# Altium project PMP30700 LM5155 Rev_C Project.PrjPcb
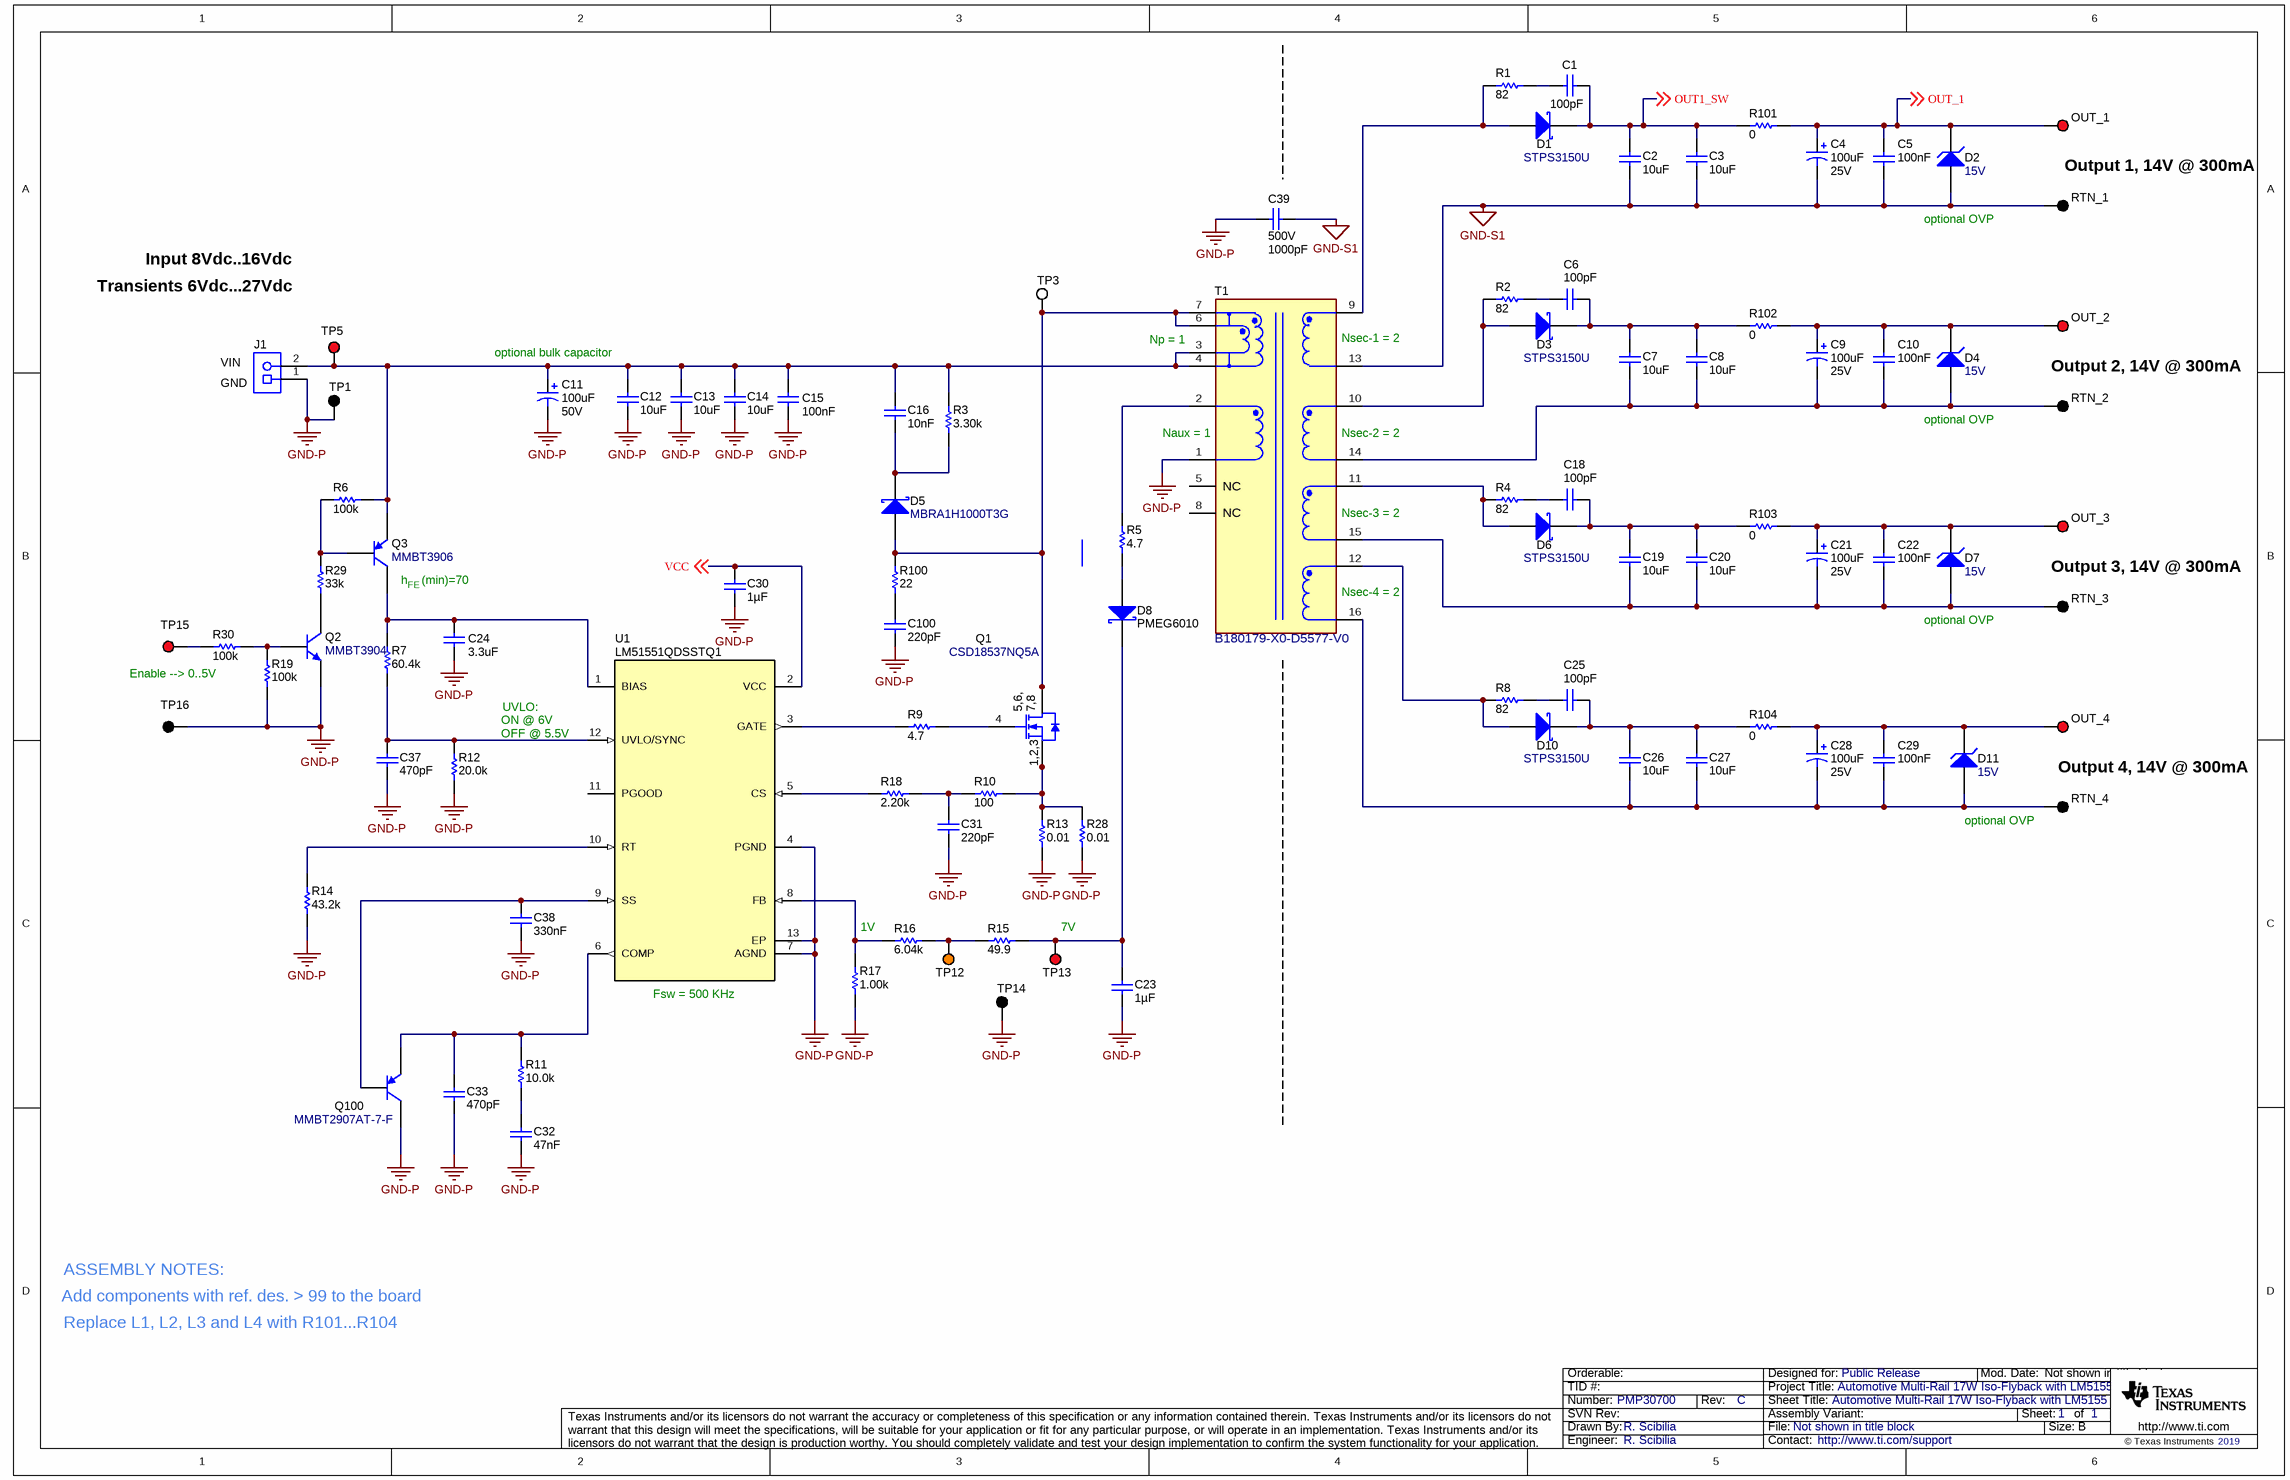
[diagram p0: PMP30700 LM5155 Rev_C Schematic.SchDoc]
CopyrightYear: 2019; PCB_Layout: PMP30700 LM5155; PCB_Rev: A; PRJ_Customer: Public Release; PRJ_Engineer: R. Scibilia; PRJ_Number: PMP30700; PRJ_Title: Automotive Multi-Rail 17W Iso-Flyback with LM5155; SCH_Rev: C; TechSupport: http://www.ti.com/support
1 sheet, 96 parts. Net scope: global (net labels, ports and power ports of the same name join across sheets).
Board file: PMP30700 Rev_A PCB.PcbDoc

## Sheet PMP30700 LM5155 Rev_C Schematic.SchDoc: Automotive Multi-Rail 17W Iso-Flyback with LM5155
size 431 x 279 mm; Date: Not shown in title block; ApprovedBy: Not shown in title block; CheckedBy: Not shown in title block; Author: Not shown in title block; CompanyName: Not shown in title block; DrawnBy: R. Scibilia; Engineer: Not shown in title block; Organization: Not shown in title block; Address1: Not shown in title block; Address2: Not shown in title block; Address3: Not shown in title block; Address4: Not shown in title block; DocumentNumber: 1; Revision: Use project parameter SCH_Rev; SheetNumber: 1; SheetTotal: 1; PageSetup: Record=PageOptions¦CenterHorizontal=True¦CenterVertical=True¦PrintScale=1.00¦XCorrection=1.00¦YCorrection=1.00¦PrintKind=0¦BorderSize=5000000¦LeftOffset=0¦BottomOffset=0¦Orientation=2¦PaperLength=1000¦PaperWidth=1000¦Scale=100¦PaperSource=15¦PrintQuality=600¦MediaType=1¦DitherType=10¦PaperKind=Letter¦PrintScaleMode=1

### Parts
C1  ValueDisplayed: 100pF  [0805_HV]  (hidden comment: GRM21A5C2E101JW01D)
C2  ValueDisplayed: 10uF  [1210_270]  (hidden comment: GRM32ER71H106KA12L)
C3  ValueDisplayed: 10uF  [1210_270]  (hidden comment: GRM32ER71H106KA12L)
C4  VDC_V: 25V  ValueDisplayed: 100uF  [SVPF_E7]  (hidden comment: 25SVPF100M)
C5  Cap_F: 100nF  [0603]  (hidden comment: GCM188R71H104KA57D)
C6  ValueDisplayed: 100pF  [0805_HV]  (hidden comment: GRM21A5C2E101JW01D)
C7  ValueDisplayed: 10uF  [1210_270]  (hidden comment: GRM32ER71H106KA12L)
C8  ValueDisplayed: 10uF  [1210_270]  (hidden comment: GRM32ER71H106KA12L)
C9  VDC_V: 25V  ValueDisplayed: 100uF  [SVPF_E7]  (hidden comment: 25SVPF100M)
C10  Cap_F: 100nF  [0603]  (hidden comment: GCM188R71H104KA57D)
C11  VDC_V: 50V  ValueDisplayed: 100uF  [Panasonic_G]  (hidden comment: EEH-ZC1H101P)
C12  ValueDisplayed: 10uF  [1210_270]  (hidden comment: GRM32ER71H106KA12L)
C13  ValueDisplayed: 10uF  [1210_270]  (hidden comment: GRM32ER71H106KA12L)
C14  ValueDisplayed: 10uF  [1210_270]  (hidden comment: GRM32ER71H106KA12L)
C15  Cap_F: 100nF  [0603]  (hidden comment: GCM188R71H104KA57D)
C16  Cap_F: 10nF  [0805_HV]  (hidden comment: GRM21BR72A103MA01L)
C18  ValueDisplayed: 100pF  [0805_HV]  (hidden comment: GRM21A5C2E101JW01D)
C19  ValueDisplayed: 10uF  [1210_270]  (hidden comment: GRM32ER71H106KA12L)
C20  ValueDisplayed: 10uF  [1210_270]  (hidden comment: GRM32ER71H106KA12L)
C21  VDC_V: 25V  ValueDisplayed: 100uF  [SVPF_E7]  (hidden comment: 25SVPF100M)
C22  Cap_F: 100nF  [0603]  (hidden comment: GCM188R71H104KA57D)
C23  Cap_F: 1µF  [0603]  (hidden comment: GRM188R71E105KA12D)
C24  ValueDisplayed: 3.3uF  [1206_190]  (hidden comment: C3216X7S2A335M160AB)
C25  ValueDisplayed: 100pF  [0805_HV]  (hidden comment: GRM21A5C2E101JW01D)
C26  ValueDisplayed: 10uF  [1210_270]  (hidden comment: GRM32ER71H106KA12L)
C27  ValueDisplayed: 10uF  [1210_270]  (hidden comment: GRM32ER71H106KA12L)
C28  VDC_V: 25V  ValueDisplayed: 100uF  [SVPF_E7]  (hidden comment: 25SVPF100M)
C29  Cap_F: 100nF  [0603]  (hidden comment: GCM188R71H104KA57D)
C30  Cap_F: 1µF  [0603]  (hidden comment: GRM188R71E105KA12D)
C31  Cap_F: 220pF  [0603]  (hidden comment: GRM188R71H221KA01D)
C32  Cap_F: 47nF  [0603]  (hidden comment: 06033C473JAT2A)
C33  ValueDisplayed: 470pF  [0603]  (hidden comment: GRM1885C1H471JA01D)
C37  ValueDisplayed: 470pF  [0603]  (hidden comment: GRM1885C1H471JA01D)
C38  Cap_F: 330nF  [0603]  (hidden comment: C1608X7R1H334K080AC)
C39  VDC_V: 500V  ValueDisplayed: 1000pF  [1210]  (hidden comment: VJ1210Y102KXEAT5Z)
C100  Cap_F: 220pF  [0603]  (hidden comment: 06031C221KAT2A)
D1  STPS3150U  [SMB]
D2  value 15V  [SOD-123]  (hidden comment: MMSZ5245B-7-F)
D3  STPS3150U  [SMB]
D4  value 15V  [SOD-123]  (hidden comment: MMSZ5245B-7-F)
D5  MBRA1H1000T3G  [SMA]
D6  STPS3150U  [SMB]
D7  value 15V  [SOD-123]  (hidden comment: MMSZ5245B-7-F)
D8  value PMEG6010  [SOD-323F]  (hidden comment: PMEG6010CEJ,115)
D10  STPS3150U  [SMB]
D11  value 15V  [SOD-123]  (hidden comment: MMSZ5245B-7-F)
J1  ED555/2DS  [TERM_BLK_ED555-2DS]  (value not drawn)
OUT_1  5000  [Keystone5000]  (value not drawn)
OUT_2  5000  [Keystone5000]  (value not drawn)
OUT_3  5000  [Keystone5000]  (value not drawn)
OUT_4  5000  [Keystone5000]  (value not drawn)
Q1  CSD18537NQ5A  [DQJ0008A]
Q2  MMBT3904  [SOT-23]
Q3  MMBT3906  [SOT-23]
Q100  MMBT2907AT-7-F  [SOT-523]
R1  ValueDisplayed: 82  [0805_HV]  (hidden comment: ERJ-6GEYJ820V)
R2  ValueDisplayed: 82  [0805_HV]  (hidden comment: ERJ-6GEYJ820V)
R3  ValueDisplayed: 3.30k  [1206]  (hidden comment: RC1206FR-073K3L)
R4  ValueDisplayed: 82  [0805_HV]  (hidden comment: ERJ-6GEYJ820V)
R5  ValueDisplayed: 4.7  [0805_HV]  (hidden comment: CRCW08054R70JNEA)
R6  ValueDisplayed: 100k  [0603]  (hidden comment: CRCW0603100KFKEA)
R7  ValueDisplayed: 60.4k  [0603]  (hidden comment: CRCW060360K4FKEA)
R8  ValueDisplayed: 82  [0805_HV]  (hidden comment: ERJ-6GEYJ820V)
R9  ValueDisplayed: 4.7  [0805_HV]  (hidden comment: CRCW08054R70JNEA)
R10  ValueDisplayed: 100  [0603]  (hidden comment: CRCW0603100RFKEA)
R11  ValueDisplayed: 10.0k  [0603]  (hidden comment: CRCW060310K0FKEA)
R12  ValueDisplayed: 20.0k  [0603]  (hidden comment: CRCW060320K0FKEA)
R13  ValueDisplayed: 0.01  [1206]  (hidden comment: CSR1206FK10L0)
R14  ValueDisplayed: 43.2k  [0603]  (hidden comment: CRCW060343K2FKEA)
R15  ValueDisplayed: 49.9  [0603]  (hidden comment: CRCW060349R9FKEA)
R16  ValueDisplayed: 6.04k  [0603]  (hidden comment: CRCW06036K04FKEA)
R17  ValueDisplayed: 1.00k  [0603]  (hidden comment: CRCW06031K00FKEA)
R18  ValueDisplayed: 2.20k  [0603]  (hidden comment: RC0603FR-072K2L)
R19  ValueDisplayed: 100k  [0603]  (hidden comment: CRCW0603100KFKEA)
R28  ValueDisplayed: 0.01  [1206]  (hidden comment: CSR1206FK10L0)
R29  ValueDisplayed: 33k  [0805_HV]  (hidden comment: ERJ-6GEYJ333V)
R30  ValueDisplayed: 100k  [0603]  (hidden comment: CRCW0603100KFKEA)
R100  ValueDisplayed: 22  [1206]  (hidden comment: CRCW120622R0JNEA)
R101  ValueDisplayed: 0  [1206]  (hidden comment: MCR18EZHJ000)
R102  ValueDisplayed: 0  [1206]  (hidden comment: MCR18EZHJ000)
R103  ValueDisplayed: 0  [1206]  (hidden comment: MCR18EZHJ000)
R104  ValueDisplayed: 0  [1206]  (hidden comment: MCR18EZHJ000)
RTN_1  5001  [Keystone5001]  (value not drawn)
RTN_2  5001  [Keystone5001]  (value not drawn)
RTN_3  5001  [Keystone5001]  (value not drawn)
RTN_4  5001  [Keystone5001]  (value not drawn)
T1  B180179-X0-D5577-V0  [FP-B180179-X0-D5577-V0_TRANSFORMER_SMD_16-MFG]
TP1  5001  [Keystone5001]  (value not drawn)
TP3  5002  [Keystone5002]  (value not drawn)
TP5  5000  [Keystone5000]  (value not drawn)
TP12  5003  [Keystone5003]  (value not drawn)
TP13  5000  [Keystone5000]  (value not drawn)
TP14  5001  [Keystone5001]  (value not drawn)
TP15  5000  [Keystone5000]  (value not drawn)
TP16  5001  [Keystone5001]  (value not drawn)
U1  LM51551QDSSTQ1  [DSS0012C]

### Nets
GND-P: C11.2(-) C12.2 C13.2 C14.2 C15.2 C23.2 C24.2 C30.2 C31.2 C32.2 C33.2 C37.2 C38.2 C39.2 C100.2 J1.1 Q2.2(E) Q100.3(C) R12.1 R13.1 R14.1 R17.1 R19.1 R28.1 T1.1 TP1.1 TP14.1 TP16.1 U1.4(PGND) U1.7(AGND) U1.13(EP)
GND-S1: C2.2 C3.2 C4.2(-) C5.2 C39.1 D2.2(A) RTN_1.1 T1.13
OUT1_SW: C1.1 C2.1 C3.1 D1.1(K) R101.1 ; off-sheet OUT1_SW
OUT_1: C4.1(+) C5.1 D2.1(K) OUT_1.1 R101.2 ; off-sheet OUT_1
VCC: C30.1 U1.2(VCC) ; off-sheet VCC
NetC1_2: C1.2 R1.2
NetC6_1: C6.1 C7.1 C8.1 D3.1(K) R102.1
NetC6_2: C6.2 R2.2
NetC7_2: C7.2 C8.2 C9.2(-) C10.2 D4.2(A) RTN_2.1 T1.14
NetC9_1: C9.1(+) C10.1 D4.1(K) OUT_2.1 R102.2
NetC11_1: C11.1(+) C12.1 C13.1 C14.1 C15.1 C16.1 J1.2 Q3.2(E) R3.2 R6.1 T1.3 T1.4 TP5.1
NetC16_2: C16.2 D5.1(K) R3.1
NetC18_1: C18.1 C19.1 C20.1 D6.1(K) R103.1
NetC18_2: C18.2 R4.2
NetC19_2: C19.2 C20.2 C21.2(-) C22.2 D7.2(A) RTN_3.1 T1.15
NetC21_1: C21.1(+) C22.1 D7.1(K) OUT_3.1 R103.2
NetC23_1: C23.1 D8.1(K) R15.2 TP13.1
NetC24_1: C24.1 Q3.3(C) R7.2 U1.1(BIAS)
NetC25_1: C25.1 C26.1 C27.1 D10.1(K) R104.1
NetC25_2: C25.2 R8.2
NetC26_2: C26.2 C27.2 C28.2(-) C29.2 D11.2(A) RTN_4.1 T1.16
NetC28_1: C28.1(+) C29.1 D11.1(K) OUT_4.1 R104.2
NetC31_1: C31.1 R10.1 R18.2
NetC32_1: C32.1 R11.1
NetC33_1: C33.1 Q100.2(E) R11.2 U1.6(COMP)
NetC37_1: C37.1 R7.1 R12.2 U1.12(UVLO/SYNC)
NetC38_1: C38.1 Q100.1(B) U1.9(SS)
NetC100_1: C100.1 R100.1
NetD1_2: D1.2(A) R1.1 T1.9
NetD3_2: D3.2(A) R2.1 T1.10
NetD5_2: D5.2(A) Q1.5(D) Q1.6(D) Q1.7(D) Q1.8(D) Q1.9(D) R100.2 T1.6 T1.7 TP3.1
NetD6_2: D6.2(A) R4.1 T1.11
NetD8_2: D8.2(A) R5.1
NetD10_2: D10.2(A) R8.1 T1.12
NetQ1_1: Q1.1(S) Q1.2(S) Q1.3(S) R10.2 R13.2 R28.2
NetQ1_4: Q1.4(G) R9.1
NetQ2_1: Q2.1(B) R19.2 R30.1
NetQ2_3: Q2.3(C) R29.1
NetQ3_1: Q3.1(B) R6.2 R29.2
NetR5_2: R5.2 T1.2
NetR9_2: R9.2 U1.3(GATE)
NetR14_2: R14.2 U1.10(RT)
NetR15_1: R15.1 R16.2 TP12.1
NetR16_1: R16.1 R17.2 U1.8(FB)
NetR18_1: R18.1 U1.5(CS)
NetR30_2: R30.2 TP15.1

Not connected (* = marked no-connect by the designer): T1 5(NC) 8(NC); U1 11(PGOOD)

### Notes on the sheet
- Output 1, 14V @ 300mA
- optional OVP
- Input 8Vdc..16Vdc
- Transients 6Vdc...27Vdc
- (near J1) VIN
- optional bulk capacitor
- (near T1) Np = 1
- (near T1) Nsec-1 = 2
- Output 2, 14V @ 300mA
- (near J1) GND
- (near T1) Naux = 1
- (near T1) Nsec-2 = 2
- (near T1) Nsec-3 = 2
- Output 3, 14V @ 300mA
- (near Q3) h    (min)=70
- (near Q3) FE
- (near T1) Nsec-4 = 2
- Enable --> 0..5V
- UVLO:
- ON @ 6V
- OFF @ 5.5V
- Output 4, 14V @ 300mA
- (near RTN_4) optional OVP
- 1V
- (near TP13) 7V
- (near U1) Fsw = 500 KHz
- ASSEMBLY NOTES:
- Add components with ref. des. > 99 to the board
- Replace L1, L2, L3 and L4 with R101...R104

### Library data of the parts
C1 C6 C18 C25 = CMP-0008236-2: CAP, CERM, 100 pF, 250 V, +/- 5%, C0G/NP0, 0805; Manufacturer: MuRata; TaMin_C: -55°C; Polarized: N; SizeAreaWB_mm2: 6.75; Value1: Unknown; U/M: EA; Value: 100pF; TaMax_C: 125°C; SizeZ_mm: 1.45; SizeX_mm: 2; SizeY_mm: 1.25; Cap_Case: 0805; Value2: 250V; SizeArea_mm2: 2.5; AEC Category: Q200
C2 C3 C7 C8 C12-C14 C19 C20 C26 C27 = CMP-0009226-3: CAP, CERM, 10 uF, 50 V, +/- 10%, X7R, 1210; Manufacturer: MuRata; TaMin_C: -55°C; Polarized: N; SizeAreaWB_mm2: 14.7; Value1: Unknown; U/M: EA; Value: 10uF; TaMax_C: 125°C; SizeZ_mm: 2.7; SizeX_mm: 3.2; SizeY_mm: 2.5; Cap_Case: 1210; Value2: 50V; SizeArea_mm2: 8; Cap_F: 10µF; AEC Category: Q200
C4 C9 C21 C28 = CMP-0012117-3: CAP, Aluminum Polymer, 100 uF, 25 V, +/- 20%, 0.024 ohm, 8.0x7.0mm SMD; Manufacturer: Panasonic; TaMin_C: -55°C; ESR_ohm: 24m; Polarized: Y; Value: 100uF; TaMax_C: 105°C; CompType: Capacitor; Cap_F: 100µF; IRMS_A: 3.2A; AEC Category: Q200
C5 C10 C15 C22 C29 = CMP-0007144-4: CAP, CERM, 0.1 uF, 50 V, +/- 10%, X7R, 0603; Manufacturer: MuRata; TaMin_C: -55°C; ESR_ohm: 20m; Polarized: N; SizeAreaWB_mm2: 4.68; Value1: 0.02 ohm; U/M: EA; Value: 0.1uF; TaMax_C: 125°C; SizeZ_mm: 1; SizeX_mm: 1.6; SizeY_mm: 0.8; Value2: 50V; SizeArea_mm2: 1.28; IRMS_A: 1.84A; AEC Category: Q200
C11 = CMP-0064994-2: CAP, Polymer Hybrid, 100 uF, 50 V,+/- 20%, 0.028 ohm, AEC-Q200 Grade 1, D10xL10.2mm SMD; Manufacturer: Panasonic; TaMin_C: -55°C; ESR_ohm: 28m; Polarized: Y; SizeAreaWB_mm2: 151.29; Value: 100uF; TaMax_C: 125°C; SizeZ_mm: 10.5; SizeX_mm: 10.3; Cap_Case: 10x10.2mm; SizeArea_mm2: 106.09; CompType: Capacitor; Cap_F: 100µF; IRMS_A: 1.6A; AEC Grade: 1; AEC Category: Q200
C16 = CMP-0008362-2: CAP, CERM, 0.01 uF, 100 V, +/- 20%, X7R, 0805; Manufacturer: MuRata; TaMin_C: -55°C; Polarized: N; SizeAreaWB_mm2: 6.75; Value1: Unknown; U/M: EA; Value: 0.01uF; TaMax_C: 125°C; SizeZ_mm: 1.45; SizeX_mm: 2; SizeY_mm: 1.25; Cap_Case: 0805; Value2: 100V; SizeArea_mm2: 2.5; AEC Category: Q200
C23 C30 = CMP-0007405-4: CAP, CERM, 1 uF, 25 V, +/- 10%, X7R, 0603; Manufacturer: MuRata; TaMin_C: -55°C; Polarized: N; SizeAreaWB_mm2: 4.68; Value1: Unknown; U/M: EA; Value: 1uF; TaMax_C: 125°C; SizeZ_mm: 1; SizeX_mm: 1.6; SizeY_mm: 0.8; Value2: 25V; SizeArea_mm2: 1.28; AEC Category: Q200
C24 = CMP-0008725-2: CAP, CERM, 3.3 uF, 100 V, +/- 20%, X7S, 1206_190; Manufacturer: TDK; TaMin_C: -55°C; ESR_ohm: 3.048m; Polarized: N; SizeAreaWB_mm2: 10.92; Value1: 0.003048 ohm; U/M: EA; Value: 3.3uF; TaMax_C: 125°C; SizeZ_mm: 1.9; SizeX_mm: 3.2; SizeY_mm: 1.6; Value2: 100V; SizeArea_mm2: 5.12; Cap_F: 3.3µF; IRMS_A: 4.157A; AEC Category: Q200
C31 = CMP-0007442-5: CAP, CERM, 220 pF, 50 V, +/- 10%, X7R, 0603; Manufacturer: MuRata; TaMin_C: -55°C; Polarized: N; SizeAreaWB_mm2: 4.68; Value1: Unknown; U/M: EA; Value: 220pF; TaMax_C: 125°C; SizeZ_mm: 1; SizeX_mm: 1.6; SizeY_mm: 0.8; Value2: 50V; SizeArea_mm2: 1.28; AEC Category: Q200
C32 = CMP-0006757-5: CAP, CERM, 0.047 uF, 25 V, +/- 5%, X7R, 0603; Manufacturer: AVX; TaMin_C: -55°C; ESR_ohm: 52m; Polarized: N; SizeAreaWB_mm2: 4.68; Value1: 0.052 ohm; U/M: EA; TaMax_C: 125°C; SizeZ_mm: 1; SizeX_mm: 1.6; SizeY_mm: 0.8; Value2: 25V; SizeArea_mm2: 1.28; AEC Category: Q200
C33 C37 = CMP-0007221-4: CAP, CERM, 470 pF, 50 V, +/- 5%, C0G/NP0, 0603; Manufacturer: MuRata; TaMin_C: -55°C; Polarized: N; SizeAreaWB_mm2: 4.68; Value1: Unknown; U/M: EA; Value: 470pF; TaMax_C: 125°C; SizeZ_mm: 1; SizeX_mm: 1.6; SizeY_mm: 0.8; Value2: 50V; SizeArea_mm2: 1.28; AEC Category: Q200
C38 = CMP-0007048-4: CAP, CERM, 0.33 uF, 50 V, +/- 10%, X7R, 0603; Manufacturer: TDK; TaMin_C: -55°C; ESR_ohm: 16.574m; Polarized: N; SizeAreaWB_mm2: 4.68; Value1: 0.016574 ohm; U/M: EA; Value: 0.33uF; TaMax_C: 125°C; SizeZ_mm: 1; SizeX_mm: 1.6; SizeY_mm: 0.8; Value2: 50V; SizeArea_mm2: 1.28; IRMS_A: 1.2837A; AEC Category: Q200
C39 = CMP-0009270-2: CAP, CERM, 1000 pF, 500 V, +/- 10%, X7R, 1210; Manufacturer: Vishay-Vitramon; TaMin_C: -55°C; Polarized: N; SizeAreaWB_mm2: 14.7; Value1: Unknown; U/M: EA; Value: 1000pF; TaMax_C: 125°C; SizeZ_mm: 1.35; SizeX_mm: 3.2; SizeY_mm: 2.5; SizeArea_mm2: 8; Cap_F: 1nF; AEC Category: Q200
C100 = CMP-0006735-5: CAP, CERM, 220 pF, 100 V, +/- 10%, X7R, 0603; Manufacturer: AVX; TaMin_C: -55°C; ESR_ohm: 0.579; Polarized: N; SizeAreaWB_mm2: 4.68; Value1: 0.579 ohm; U/M: EA; Value: 220pF; TaMax_C: 125°C; SizeZ_mm: 1; SizeX_mm: 1.6; SizeY_mm: 0.8; Value2: 100V; SizeArea_mm2: 1.28; AEC Category: Q200
D1 D3 D6 D10 = CMP-0028766-2: Diode, Schottky, 150 V, 3 A, SMB; Manufacturer: STMicroelectronics; AEC Category: Q101; Vr_V: 150V; TJmax_C: 150°C; SizeX_mm: 5.6; SizeZ_mm: 2.6; Vf_V: 670mV; Green_REACh: Passed; SizeAreaWB_mm2: 44.156; Green_Lifecycle: Active; Value2: 0.67V; Value1: 3A; AEC Qualified: N; SizeY_mm: 3.81; SizeArea_mm2: 21.336
D2 D4 D7 D11 = CMP-0005753-4: Diode, Zener, 15 V, 500 mW, SOD-123; Manufacturer: Diodes Inc.; RJA_CperW: 350; SizeX_mm: 3.85; SizeArea_mm2: 6.545; SizeZ_mm: 1.35; Value1: 0.5W; Power_W: 500mW; SizeAreaWB_mm2: 13.095; AEC Category: Q101; SizeY_mm: 1.7
D5 = CMP-0028550-2: Diode, Schottky, 40 V, 1 A, SMA; Manufacturer: ON Semiconductor; Io_A: 1A; Value: MBRA1H100T3G; SizeArea_mm2: 16.3228; Value2: 0.55V; SizeY_mm: 2.92; AEC Category: Q101; SizeZ_mm: 2.87; Vf_V: 550mV; Green_REACh: Incomplete; RJC_CperW: 35; SizeAreaWB_mm2: 37.3428; TJmax_C: 125°C; SizeX_mm: 5.59; Vr_V: 100V; Green_Lifecycle: Not Set
D8 = CMP-0077011-2: Diode, Schottky, 60 V, 1 A, SOD-323F; Manufacturer: Nexperia; SizeX_mm: 2.5; TJmax_C: 150°C; SizeZ_mm: 0.8; Vr_V: 60V; Green_Lifecycle: Not Set; Value2: 0.66V; SizeAreaWB_mm2: 7.875; Green_REACh: Incomplete; Io_A: 1A; SizeY_mm: 1.25; SizeArea_mm2: 3.125; Vf_V: 660mV; AEC Category: Q101
J1 = CMP-0074913-1: Terminal Block, 3.5mm Pitch, 2x1, TH; Manufacturer: On-Shore Technology; Cert_VDE: Y; CNHeader: False; Current_A: 6A; Green_Lifecycle: Active; Shrouded: N; Gender: Female; Green_REACh: Passed; Voltage_V: 150V; Row_Count: 1; Pitch_mm: 3.5; ContactFinish: Brass; CT: True
OUT_1-OUT_4 TP5 TP13 TP15 = CMP-0055137-1: Test Point, Miniature, Red, TH; Manufacturer: Keystone; CNHeader: FALSE; Green_Lifecycle: Active; Green_REACh: Passed; ContactFinish: Silver; CT: TRUE
Q1 = CMP-0000822-1: MOSFET, N-CH, 60 V, 50 A, DQJ0008A (VSONP-8); Alternate Manufacturer: None; Manufacturer: Texas Instruments; SizeZ_mm: 1.1; ChType: N; Value2: 14 nC; Value1: 0.03; VdsMax_V: 60V; SizeX_mm: 6; SizeY_mm: 4.9; Vgs_V: 20V; Value: 60V; Rdson45_ohm: 36m; SizeArea_mm2: 29.4; AEC Category: Q101; IdsMax_A: 50A; SizeAreaWB_mm2: 55.2; U/M: EA; QgTyp_nC: 14
Q2 = CMP-0000386-1: Transistor, NPN, 40 V, 0.2 A, SOT-23; Manufacturer: Fairchild Semiconductor; TaMax_C: 150°C; Value2: 300; Value1: 0.2 A; Vcesat1_V: 200mV; SizeX_mm: 2.5; SizeY_mm: 3; TaMin_C: -55°C; IcRated_A: 200mA; CompType: BJT; SizeZ_mm: 1.1; Value: 40 V; SizeArea_mm2: 7.5; NPN: 1; Vceo_V: 40V; PNP: 0; AEC Category: Q101; SizeAreaWB_mm2: 14; U/M: EA
Q3 = CMP-0000325-2: Transistor, PNP, 40 V, 0.2 A, SOT-23; Manufacturer: Fairchild Semiconductor; TaMax_C: 150°C; Value2: 300; Value1: 0.2 A; Vcesat1_V: 250mV; SizeX_mm: 2.5; SizeY_mm: 3; TaMin_C: -55°C; IcRated_A: 200mA; CompType: BJT; SizeZ_mm: 1.1; Value: 40 V; SizeArea_mm2: 7.5; NPN: 0; Vceo_V: 40V; PNP: 1; AEC Category: Q101; SizeAreaWB_mm2: 14; U/M: EA
Q100 = CMP-0000362-2: Transistor, PNP, 60 V, 0.6 A, AEC-Q101, SOT-523; Manufacturer: Diodes Inc.; TaMax_C: 150°C; Value2: 300; Value1: 0.6 A; Vcesat1_V: 400mV; SizeX_mm: 1.6; TaMin_C: -55°C; IcRated_A: 600mA; CompType: BJT; SizeZ_mm: 0.8; AEC Qualified: Y; Value: 60 V; SizeArea_mm2: 2.56; NPN: 0; Vceo_V: 60V; PNP: 1; AEC Category: Q101; SizeAreaWB_mm2: 6.76; U/M: EA
R1 R2 R4 R8 = CMP-0020773-3: RES, 82, 5%, 0.125 W, AEC-Q200 Grade 0, 0805; Manufacturer: Panasonic; Power_W: 125mW; TempCo: 200 ppm/C; Value_Code: 82R0; Value: 82; EIA_Code: E24; SizeX_mm: 2; SizeY_mm: 1.25; SizeZ_mm: 1.45; Value2: 0.125W; SizeArea_mm2: 2.5; AEC Qualified: Y; VDC_V: 150V; AEC Category: Q200; AEC Grade: 0; SizeAreaWB_mm2: 6.75
R3 = CMP-0018254-2: RES, 3.30 k, 1%, 0.25 W, 1206; Manufacturer: Yageo America; Power_W: 250mW; TempCo: 100 ppm/C; Value_Code: 3k30; U/M: EA; Value: 3.30k; Res_ohm: 3.3k; SizeX_mm: 3.2; SizeY_mm: 1.6; SizeZ_mm: 1.35; Value2: 0.25W; SizeArea_mm2: 5.12; VDC_V: 200V; AEC Category: Q200
R5 R9 = CMP-0020563-2: RES, 4.7, 5%, 0.125 W, 0805; Manufacturer: Vishay-Dale; Power_W: 125mW; TempCo: 200 ppm/C; Value_Code: 4R70; U/M: EA; Value: 4.7; EIA_Code: E24; SizeX_mm: 2; SizeY_mm: 1.25; SizeZ_mm: 1.45; Value2: 0.125W; SizeArea_mm2: 2.5; VDC_V: 150V; AEC Category: Q200
R6 R19 R30 = CMP-0021990-4: RES, 100 k, 1%, 0.1 W, AEC-Q200 Grade 0, 0603; Manufacturer: Vishay-Dale; Power_W: 100mW; TempCo: 100 ppm/C; Value: 100k; EIA_Code: E96; SizeX_mm: 1.6; SizeY_mm: 0.8; SizeZ_mm: 1; Value2: 0.1W; SizeArea_mm2: 1.28; AEC Qualified: Y; VDC_V: 75V; AEC Category: Q200; AEC Grade: 0
R7 = CMP-0022532-4: RES, 60.4 k, 1%, 0.1 W, AEC-Q200 Grade 0, 0603; Manufacturer: Vishay-Dale; Power_W: 100mW; TempCo: 100 ppm/C; Value_Code: 60k4; Value: 60.4k; EIA_Code: E96; SizeX_mm: 1.6; SizeY_mm: 0.8; SizeZ_mm: 1; Value2: 0.1W; SizeArea_mm2: 1.28; AEC Qualified: Y; VDC_V: 75V; AEC Category: Q200; AEC Grade: 0
R10 = CMP-0021991-3: RES, 100, 1%, 0.1 W, 0603; Manufacturer: Vishay-Dale; Power_W: 100mW; TempCo: 100 ppm/C; Value_Code: 100R; U/M: EA; Value: 100; EIA_Code: E96; SizeX_mm: 1.6; SizeY_mm: 0.8; SizeZ_mm: 1; Value2: 0.1W; SizeArea_mm2: 1.28; VDC_V: 75V; AEC Category: Q200
R11 = CMP-0021998-3: RES, 10.0 k, 1%, 0.1 W, 0603; Manufacturer: Vishay-Dale; Power_W: 100mW; TempCo: 100 ppm/C; Value_Code: 10k0; U/M: EA; Value: 10.0k; EIA_Code: E96; Res_ohm: 10k; SizeX_mm: 1.6; SizeY_mm: 0.8; SizeZ_mm: 1; Value2: 0.1W; SizeArea_mm2: 1.28; VDC_V: 75V; AEC Category: Q200
R12 = CMP-0022204-4: RES, 20.0 k, 1%, 0.1 W, AEC-Q200 Grade 0, 0603; Manufacturer: Vishay-Dale; Power_W: 100mW; TempCo: 100 ppm/C; Value_Code: 20k0; Value: 20.0k; EIA_Code: E96; Res_ohm: 20k; SizeX_mm: 1.6; SizeY_mm: 0.8; SizeZ_mm: 1; Value2: 0.1W; SizeArea_mm2: 1.28; AEC Qualified: Y; VDC_V: 75V; AEC Category: Q200; AEC Grade: 0
R13 R28 = CMP-0017256-2: RES, 0.01, 1%, 0.5 W, 1206; Manufacturer: Stackpole Electronics Inc; Power_W: 500mW; TempCo: 100 ppm/C; Value_Code: R010; U/M: EA; Value: 0.01; EIA_Code: E96; Res_ohm: 10m; SizeX_mm: 3.2; SizeY_mm: 1.6; SizeZ_mm: 1.35; Value2: 0.5W; SizeArea_mm2: 5.12; AEC Category: Q200
R14 = CMP-0022422-4: RES, 43.2 k, 1%, 0.1 W, AEC-Q200 Grade 0, 0603; Manufacturer: Vishay-Dale; Power_W: 100mW; TempCo: 100 ppm/C; Value_Code: 43k2; Value: 43.2k; EIA_Code: E96; SizeX_mm: 1.6; SizeY_mm: 0.8; SizeZ_mm: 1; Value2: 0.1W; SizeArea_mm2: 1.28; AEC Qualified: Y; VDC_V: 75V; AEC Category: Q200; AEC Grade: 0
R15 = CMP-0022448-3: RES, 49.9, 1%, 0.1 W, 0603; Manufacturer: Vishay-Dale; Power_W: 100mW; TempCo: 100 ppm/C; Value_Code: 49R9; U/M: EA; Value: 49.9; EIA_Code: E96; SizeX_mm: 1.6; SizeY_mm: 0.8; SizeZ_mm: 1; Value2: 0.1W; SizeArea_mm2: 1.28; VDC_V: 75V; AEC Category: Q200
R16 = CMP-0022558-4: RES, 6.04 k, 1%, 0.1 W, AEC-Q200 Grade 0, 0603; Manufacturer: Vishay-Dale; Power_W: 100mW; TempCo: 100 ppm/C; Value_Code: 6k04; Value: 6.04k; EIA_Code: E96; SizeX_mm: 1.6; SizeY_mm: 0.8; SizeZ_mm: 1; Value2: 0.1W; SizeArea_mm2: 1.28; AEC Qualified: Y; VDC_V: 75V; AEC Category: Q200; AEC Grade: 0
R17 = CMP-0022109-4: RES, 1.00 k, 1%, 0.1 W, 0603; Manufacturer: Vishay-Dale; Power_W: 100mW; TempCo: 100 ppm/C; Value_Code: 1k00; U/M: EA; Value: 1.00k; EIA_Code: E96; Res_ohm: 1k; SizeX_mm: 1.6; SizeY_mm: 0.8; SizeZ_mm: 1; Value2: 0.1W; SizeArea_mm2: 1.28; VDC_V: 75V; AEC Category: Q200
R18 = CMP-0022986-5: RES, 2.20 k, 1%, 0.1 W, 0603; Manufacturer: Yageo; Power_W: 100mW; TempCo: 100 ppm/C; Value_Code: 2k20; Value: 2.20k; Res_ohm: 2.2k; SizeX_mm: 1.6; SizeY_mm: 0.8; SizeZ_mm: 1; Value2: 0.1W; SizeArea_mm2: 1.28; AEC Qualified: N; VDC_V: 75V; AEC Category: Q200; SizeAreaWB_mm2: 4.68
R29 = CMP-0020705-3: RES, 33 k, 5%, 0.125 W, AEC-Q200 Grade 0, 0805; Manufacturer: Panasonic; Power_W: 125mW; TempCo: 200 ppm/C; Value_Code: 33k0; Value: 33k; EIA_Code: E24; SizeX_mm: 2; SizeY_mm: 1.25; SizeZ_mm: 1.45; Value2: 0.125W; SizeArea_mm2: 2.5; AEC Qualified: Y; VDC_V: 150V; AEC Category: Q200; AEC Grade: 0; SizeAreaWB_mm2: 6.75
R100 = CMP-0018631-3: RES, 22, 5%, 0.25 W, AEC-Q200 Grade 0, 1206; Manufacturer: Vishay-Dale; Power_W: 250mW; TempCo: 200 ppm/C; Value_Code: 22R0; Value: 22; EIA_Code: E24; SizeX_mm: 3.2; SizeY_mm: 1.6; SizeZ_mm: 1.35; Value2: 0.25W; SizeArea_mm2: 5.12; AEC Qualified: Y; VDC_V: 200V; AEC Category: Q200; AEC Grade: 0
R101-R104 = CMP-0018756-2: RES, 0, 5%, 0.25 W, 1206; Manufacturer: Rohm; Power_W: 250mW; TempCo: 200 ppm/C; Value_Code: 0000; U/M: EA; Value: 0; EIA_Code: E24; SizeX_mm: 3.2; SizeY_mm: 1.6; SizeZ_mm: 1.35; Value2: 0.25W; SizeArea_mm2: 5.12; VDC_V: 200V; AEC Category: Q200
RTN_1-RTN_4 TP1 TP14 TP16 = CMP-0055138-1: Test Point, Miniature, Black, TH; Manufacturer: Keystone; CNHeader: FALSE; Green_Lifecycle: Active; Green_REACh: Passed; ContactFinish: Silver; CT: TRUE
T1 = CMP-0086715-1: EE19 16 Pin Transformer; Manufacturer: Bourns; SizeZ_mm: 15.3mm; DCR_ohm: 10m; Ns1toNp: 1:2/1:1; AEC Qualified: Yes; Ind_H: 5mH; AEC Grade: Grade 1
TP3 = CMP-0055139-1: Test Point, Miniature, White, TH; Manufacturer: Keystone; CNHeader: FALSE; Green_Lifecycle: Active; Green_REACh: Passed; ContactFinish: Silver; CT: TRUE
TP12 = CMP-0055140-1: Test Point, Miniature, Orange, TH; Manufacturer: Keystone; CNHeader: FALSE; Green_Lifecycle: Active; Green_REACh: Passed; ContactFinish: Silver; CT: TRUE
U1 = CMP-0081540-1: Automotive Grade 2.2-MHz Wide Input Non-synchronous Boost Controller, DSS0012C (WSON-12); Alternate PartNumber: LM51551QDSSRQ1; Alternate Manufacturer: Texas Instruments; SizeAreaWB_mm2: 12; SizeZ_mm: 0.8; SizeX_mm: 2; SizeY_mm: 3; SizeArea_mm2: 6; CompType: IC; AEC Qualified: Y; AEC Category: Q200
